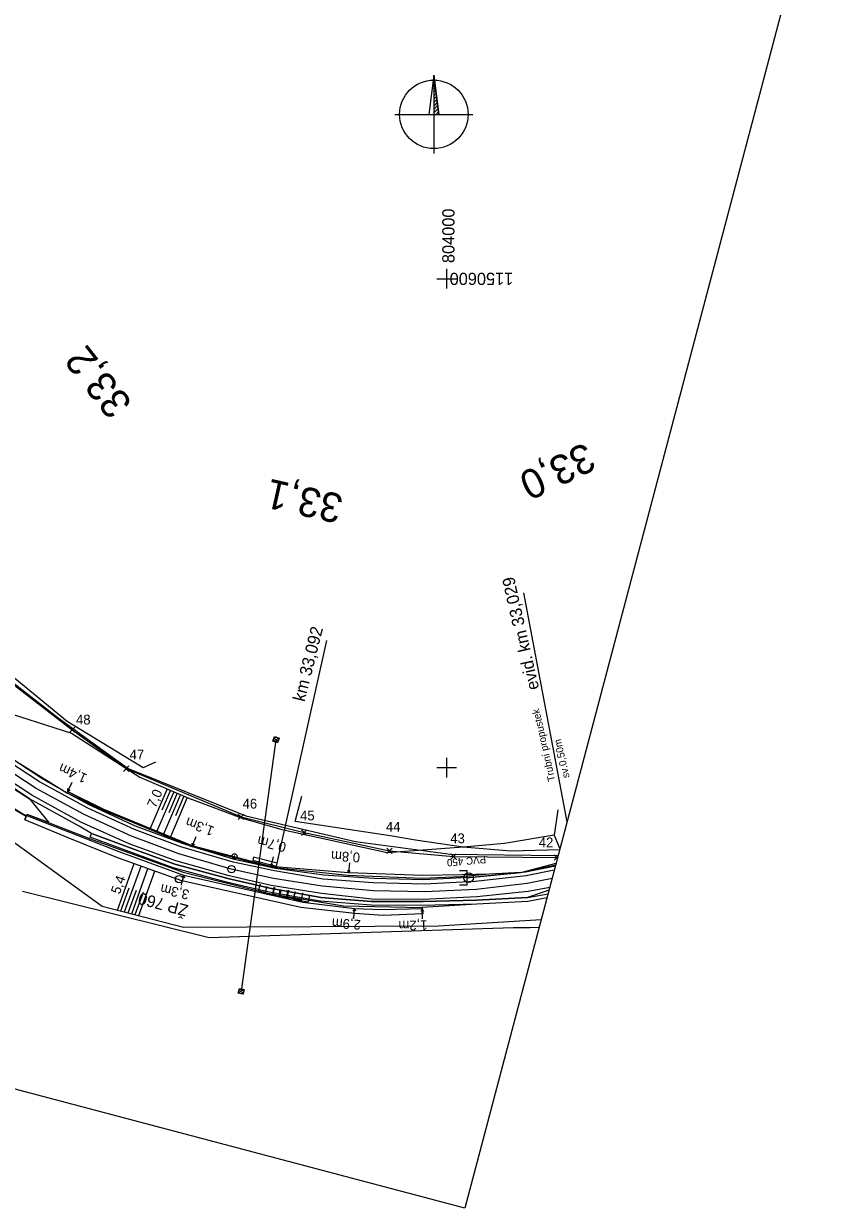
# Model space of a CAD drawing. Extents: x -805011 to -803920, y -1150790 to -1150234.
# Drawn here: x -804086.5 to -803920.3, y -1150790.1 to -1150547.8 of the extents above; entities that cross this region are included whole.
import ezdxf

# ---------------------------------------------------------------- set-up
doc = ezdxf.new("R2010")
doc.units = 0
for name, color, linetype in [('0381KM032-037P - Vrstva 1', 7, 'Continuous'), ('0381KM032-037P - Vrstva 11', 7, 'Continuous'), ('0381KM032-037P - Vrstva 13', 7, 'Continuous'), ('0381KM032-037P - Vrstva 17', 7, 'Continuous'), ('0381KM032-037P - Vrstva 19', 7, 'Continuous'), ('0381KM032-037P - Vrstva 25', 7, 'Continuous'), ('0381KM032-037P - Vrstva 4', 7, 'Continuous'), ('0381KM032-037P - Vrstva 43', 7, 'Continuous'), ('0381KM032-037P - Vrstva 44', 7, 'Continuous'), ('0381KM032-037P - Vrstva 48', 7, 'Continuous'), ('0381KM032-037P - Vrstva 49', 7, 'Continuous'), ('0381KM032-037P - Vrstva 7', 7, 'Continuous'), ('0381KM032-037P - Vrstva 9', 7, 'Continuous'), ('Default', 7, 'Continuous'), ('formát', 7, 'Continuous'), ('hran DP - hran DP', 7, 'Continuous'), ('krizky_1000 - souradnice', 7, 'Continuous'), ('krizky_1000 - Vrstva 1', 7, 'Continuous'), ('PSR_C2_2_Lomove_body_Vimperk - Vrstva 60', 7, 'Continuous'), ('PSR_C2_2_trasa_Vimperk - Kabelová trasa', 7, 'Continuous'), ('vyt_sit - stávající', 7, 'Continuous')]:
    doc.layers.add(name, color=color, linetype=linetype)

msp = doc.modelspace()

# ---------------------------------------------------------------- linework, layer by layer
at = {"layer": '0381KM032-037P - Vrstva 1'}
msp.add_lwpolyline([(-803978.41, -1150722.71), (-803983.51, -1150723.68), (-803993.92, -1150724.91), (-804004.46, -1150725.42), (-804014.95, -1150725.21), (-804025.47, -1150724.25), (-804035.41, -1150722.67), (-804044.08, -1150720.74), (-804054.77, -1150717.61), (-804064.47, -1150714.03), (-804074.16, -1150709.61), (-804083.95, -1150704.25), (-804092.73, -1150698.52), (-804098.22, -1150694.46), (-804106.33, -1150687.73), (-804113.82, -1150680.6), (-804121.06, -1150672.62)], dxfattribs=at)
at = {"layer": '0381KM032-037P - Vrstva 11'}
for p, q in [((-804034.26, -1150693.99), (-804035.54, -1150694.57)), ((-804034.75, -1150693.8), (-804035.36, -1150694.08)), ((-804034.44, -1150694.48), (-804035.04, -1150694.76)), ((-804041.41, -1150745.38), (-804042.6, -1150746.13)), ((-804041.93, -1150745.26), (-804042.49, -1150745.62)), ((-804041.53, -1150745.9), (-804042.08, -1150746.25))]:
    msp.add_line(p, q, dxfattribs=at)
for points in [[(-804034.6, -1150694.92), (-804035.54, -1150694.57), (-804035.19, -1150693.64), (-804034.25, -1150693.98)], [(-804041.63, -1150746.35), (-804042.61, -1150746.13), (-804042.39, -1150745.16), (-804041.41, -1150745.38)]]:
    msp.add_lwpolyline(points, close=True, dxfattribs=at)
at = {"layer": '0381KM032-037P - Vrstva 13'}
for p, q in [((-804076.66, -1150703.07), (-804077.51, -1150704.88)), ((-804090.39, -1150707.37), (-804086.01, -1150709.92)), ((-804086.01, -1150709.9), (-804090.31, -1150707.26)), ((-804086.01, -1150709.9), (-804085.89, -1150709.55)), ((-804086.01, -1150709.92), (-804086.01, -1150709.9)), ((-804085.98, -1150709.77), (-804085.89, -1150709.55)), ((-804051.27, -1150714.14), (-804052.03, -1150715.99)), ((-804035.82, -1150720.44), (-804051.93, -1150716.22)), ((-804035.5, -1150718.26), (-804035.97, -1150720.21)), ((-804019.87, -1150719.5), (-804020.03, -1150721.49)), ((-804054.2, -1150724.02), (-804053.75, -1150722.07)), ((-804018.95, -1150730.84), (-804018.83, -1150728.85)), ((-804004.99, -1150728.9), (-804004.87, -1150729.93)), ((-804004.95, -1150730.9), (-804004.99, -1150728.9))]:
    msp.add_line(p, q, dxfattribs=at)
for points in [[(-804052.03, -1150715.99), (-804070.24, -1150708.52), (-804077.53, -1150704.87), (-804077.68, -1150705.14), (-804070.39, -1150708.64), (-804052.3, -1150716.03), (-804051.93, -1150716.22)], [(-804077.57, -1150704.3), (-804077.51, -1150704.88), (-804077.03, -1150704.55)], [(-804085.98, -1150709.77), (-804086.01, -1150709.92), (-804086.24, -1150710.7)], [(-804004.99, -1150728.9), (-804013.04, -1150729.07), (-804018.83, -1150728.85), (-804029.4, -1150727.62), (-804053.75, -1150722.07), (-804066.98, -1150717.23), (-804077.05, -1150713.27), (-804085.98, -1150709.77)], [(-804085.89, -1150709.55), (-804073.05, -1150714.48), (-804053.9, -1150721.4), (-804036.64, -1150725.7), (-804021.1, -1150728.28), (-804004.99, -1150728.61), (-804004.87, -1150729.93)], [(-804004.87, -1150729.93), (-804012.98, -1150730.26), (-804018.76, -1150729.81), (-804029.79, -1150728.64), (-804054.15, -1150723.15), (-804067.44, -1150718.36), (-804077.42, -1150714.36), (-804086.24, -1150710.7)], [(-804072.89, -1150714.19), (-804072.63, -1150713.44), (-804065.3, -1150716.18), (-804055.61, -1150719.76), (-804044.75, -1150722.66), (-804036.16, -1150724.67), (-804025.7, -1150726.54), (-804015.38, -1150727.38), (-804004.78, -1150727.4), (-803993.85, -1150727.11), (-803983.42, -1150726.57), (-803979.23, -1150725.8)], [(-803979.45, -1150726.65), (-803983.37, -1150727.37), (-803993.84, -1150727.91), (-804005.29, -1150728.22), (-804015.43, -1150728.15), (-804025.86, -1150727.31), (-804036.32, -1150725.46), (-804045.02, -1150723.43), (-804055.91, -1150720.49), (-804065.55, -1150716.94), (-804072.89, -1150714.19)], [(-804052.11, -1150715.42), (-804052.03, -1150715.99), (-804051.56, -1150715.64)], [(-803991.2, -1150721.8), (-803996.89, -1150721.92), (-804004.84, -1150722.06), (-804020.03, -1150721.49), (-804035.97, -1150720.21), (-804052.03, -1150715.99)], [(-804036.15, -1150719.65), (-804035.97, -1150720.21), (-804035.56, -1150719.79)], [(-804053.57, -1150722.62), (-804053.75, -1150722.07), (-804054.16, -1150722.49)], [(-803991.2, -1150721.8), (-803997.06, -1150722.33), (-804004.97, -1150722.65), (-804020.12, -1150722.09), (-804035.82, -1150720.44)], [(-804020.29, -1150720.97), (-804020.03, -1150721.49), (-804019.69, -1150721.02)], [(-804018.56, -1150729.36), (-804018.83, -1150728.85), (-804019.16, -1150729.33)], [(-804004.68, -1150729.4), (-804004.99, -1150728.9), (-804005.28, -1150729.41)], [(-804004.99, -1150728.9), (-804004.99, -1150728.9), (-804004.99, -1150728.9), (-804004.99, -1150728.61)]]:
    msp.add_lwpolyline(points, dxfattribs=at)
at = {"layer": '0381KM032-037P - Vrstva 17'}
for points in [[(-804059.54, -1150698.86), (-804062.04, -1150700.07), (-804077.59, -1150690.55), (-804099.12, -1150672.95)], [(-803996.63, -1150716.3), (-804006.34, -1150714.83), (-804011.55, -1150713.97), (-804030.97, -1150711.02), (-804029.61, -1150705.83)], [(-803977.22, -1150708.65), (-803977.99, -1150713.83)], [(-803977.99, -1150713.83), (-803976.8, -1150716.64)], [(-803976.84, -1150716.79), (-803986.83, -1150717.08), (-803996.63, -1150716.3)]]:
    msp.add_lwpolyline(points, dxfattribs=at)
at = {"layer": '0381KM032-037P - Vrstva 19'}
msp.add_line((-803975.34, -1150711.1), (-803984.23, -1150664.27), dxfattribs=at)
at = {"layer": '0381KM032-037P - Vrstva 25'}
msp.add_line((-804034.9, -1150694.28), (-804042.01, -1150745.75), dxfattribs=at)
at = {"layer": '0381KM032-037P - Vrstva 4'}
for points in [[(-804075.18, -1150711.95), (-804085.34, -1150706.36), (-804094.07, -1150700.58), (-804099.68, -1150696.17), (-804107.82, -1150689.29), (-804115.4, -1150682.25), (-804122.72, -1150674.01), (-804129.15, -1150665.64), (-804135, -1150656.89)], [(-804074.79, -1150711.15), (-804084.84, -1150705.62), (-804093.69, -1150699.81), (-804099.23, -1150695.65), (-804107.33, -1150688.8), (-804114.94, -1150681.73), (-804122.23, -1150673.64), (-804128.61, -1150665.3), (-804134.56, -1150656.61)], [(-804073.38, -1150708.29), (-804083.27, -1150702.88), (-804091.89, -1150697.28), (-804097.27, -1150693.2), (-804105.34, -1150686.53), (-804112.64, -1150679.57), (-804120.03, -1150671.79), (-804126.35, -1150663.48), (-804132.06, -1150655.06)], [(-804073.1, -1150707.59), (-804077.68, -1150705.14), (-804082.78, -1150702.25), (-804091.44, -1150696.56), (-804096.83, -1150692.65), (-804104.73, -1150685.98), (-804112.1, -1150679.17), (-804119.6, -1150671.34), (-804125.86, -1150663.1), (-804131.6, -1150654.76)], [(-803977.73, -1150720.15), (-803983.88, -1150721.36), (-803994.18, -1150722.4), (-804004.64, -1150722.95), (-804014.86, -1150722.69), (-804025.14, -1150721.99), (-804034.98, -1150720.62), (-804043.41, -1150718.77), (-804051.93, -1150716.22), (-804054.24, -1150715.48), (-804063.6, -1150711.99), (-804073.1, -1150707.59)], [(-803977.96, -1150721), (-803983.73, -1150722.13), (-803994.13, -1150723.26), (-804004.52, -1150723.87), (-804015.05, -1150723.54), (-804025.27, -1150722.78), (-804035.17, -1150721.13), (-804043.67, -1150719.32), (-804054.39, -1150716.19), (-804063.83, -1150712.64), (-804073.38, -1150708.29)], [(-803979.03, -1150725.06), (-803983.42, -1150726.57), (-803993.85, -1150727.11), (-804004.78, -1150727.4), (-804015.38, -1150727.38), (-804025.7, -1150726.54), (-804036.16, -1150724.67), (-804044.75, -1150722.66), (-804055.61, -1150719.76), (-804065.3, -1150716.18), (-804072.63, -1150713.44), (-804075.18, -1150711.95)], [(-803978.88, -1150724.49), (-803983.32, -1150725.37), (-803993.82, -1150726.43), (-804004.8, -1150726.96), (-804015.29, -1150726.92), (-804025.6, -1150725.76), (-804035.88, -1150724.11), (-804044.5, -1150722.13), (-804055.4, -1150719.07), (-804064.95, -1150715.56), (-804074.79, -1150711.15)]]:
    msp.add_lwpolyline(points, dxfattribs=at)
at = {"layer": '0381KM032-037P - Vrstva 43'}
for points in [[(-803997.39, -1150721.01), (-803995.89, -1150721.01), (-803995.89, -1150724.01), (-803997.39, -1150724.01)], [(-804035.17, -1150724.55), (-804035.58, -1150726), (-804038.46, -1150725.19), (-804038.06, -1150723.74)], [(-804033.84, -1150725), (-804034.23, -1150726.45), (-804037.12, -1150725.67), (-804036.73, -1150724.22)], [(-804032.32, -1150725.04), (-804032.63, -1150726.51), (-804035.56, -1150725.9), (-804035.26, -1150724.43)], [(-804031.05, -1150725.35), (-804031.24, -1150726.84), (-804034.22, -1150726.45), (-804034.02, -1150724.96)], [(-804029.49, -1150725.62), (-804029.77, -1150727.09), (-804032.72, -1150726.52), (-804032.43, -1150725.05)], [(-804028.05, -1150726.05), (-804028.31, -1150727.53), (-804031.27, -1150727.01), (-804031.01, -1150725.53)]]:
    msp.add_lwpolyline(points, dxfattribs=at)
msp.add_circle((-803995.51, -1150722.5), 1, dxfattribs=at)
at = {"layer": '0381KM032-037P - Vrstva 44'}
msp.add_lwpolyline([(-803995.89, -1150722.51), (-803984.82, -1150721.44), (-803977.57, -1150719.55)], dxfattribs=at)
at = {"layer": '0381KM032-037P - Vrstva 48'}
for p, q in [((-804057.18, -1150704.34), (-804060.65, -1150712.45)), ((-804055.8, -1150704.93), (-804059.26, -1150713.02)), ((-804056.49, -1150704.63), (-804058.22, -1150708.69)), ((-804055.11, -1150705.22), (-804056.84, -1150709.27)), ((-804054.42, -1150705.52), (-804057.88, -1150713.59)), ((-804053.04, -1150706.11), (-804056.49, -1150714.16)), ((-804053.73, -1150705.81), (-804055.46, -1150709.84)), ((-804067.33, -1150729.13), (-804063.91, -1150719.64)), ((-804065.87, -1150729.51), (-804062.5, -1150720.14)), ((-804064.41, -1150729.89), (-804061.08, -1150720.65)), ((-804062.95, -1150730.26), (-804059.67, -1150721.16)), ((-804066.6, -1150729.32), (-804064.9, -1150724.6)), ((-804065.14, -1150729.7), (-804063.46, -1150725.05)), ((-804063.68, -1150730.07), (-804062.03, -1150725.49))]:
    msp.add_line(p, q, dxfattribs=at)
at = {"layer": '0381KM032-037P - Vrstva 49'}
msp.add_line((-804001.62, -1150732.39), (-803980.62, -1150731.04), dxfattribs=at)
for points in [[(-804216.26, -1150515.03), (-804196.49, -1150533.54), (-804188.66, -1150542.31), (-804183.72, -1150548.22), (-804177, -1150556.4), (-804165.66, -1150573.06), (-804155.49, -1150590.5), (-804146.45, -1150604.86), (-804136.37, -1150622.31), (-804131.91, -1150629.82), (-804122.71, -1150645.64), (-804115.71, -1150666.79), (-804102.89, -1150677.06), (-804092.51, -1150687.92), (-804076.71, -1150692.97), (-804062.72, -1150701.97), (-804052.08, -1150706.52)], [(-804191.88, -1150555.68), (-804187.09, -1150562.15), (-804183.47, -1150572.06), (-804177.47, -1150586.83), (-804171.32, -1150602.68), (-804162.19, -1150629.63), (-804127.41, -1150694.05), (-804117.85, -1150694.76), (-804107.49, -1150702.04), (-804103.03, -1150704.73), (-804070.42, -1150728.33), (-804053.81, -1150732.63), (-804001.62, -1150732.39)], [(-804171.89, -1150581.01), (-804161.29, -1150603.14), (-804153.71, -1150619.99), (-804149.71, -1150629.27), (-804147.81, -1150633.31), (-804145.48, -1150638.07), (-804140.73, -1150647.62), (-804139.02, -1150650.67), (-804131.55, -1150663.46), (-804125.32, -1150670.91), (-804120.07, -1150678.75), (-804110.3, -1150687.62), (-804101.36, -1150694.88), (-804099.68, -1150696.17), (-804094.07, -1150700.58), (-804090.5, -1150703.01), (-804085.34, -1150706.36), (-804081.43, -1150711.18)], [(-804087.29, -1150699.16), (-804077.68, -1150705.14), (-804077.53, -1150704.87), (-804070.24, -1150708.52), (-804052.03, -1150715.99)], [(-803977.22, -1150708.65), (-803977.99, -1150713.83), (-803988.17, -1150715.55), (-803996.63, -1150716.3), (-804012.18, -1150717.41), (-804033.61, -1150712.69), (-804041.95, -1150710.32), (-804052.08, -1150706.52)], [(-803979.45, -1150726.65), (-803983.37, -1150727.37), (-803993.84, -1150727.91), (-804004.99, -1150728.61), (-804004.87, -1150729.93), (-804012.98, -1150730.26), (-804018.76, -1150729.81), (-804029.79, -1150728.64), (-804054.15, -1150723.15), (-804067.44, -1150718.36), (-804077.42, -1150714.36), (-804086.24, -1150710.7), (-804086.01, -1150709.92)], [(-804086.01, -1150709.92), (-804086.01, -1150709.9), (-804085.89, -1150709.55), (-804081.43, -1150711.18)], [(-803984.82, -1150721.44), (-803991.2, -1150721.8), (-803996.89, -1150721.92), (-804004.84, -1150722.06), (-804020.03, -1150721.49), (-804035.97, -1150720.21), (-804052.03, -1150715.99)], [(-803984.82, -1150721.44), (-803977.66, -1150719.89)]]:
    msp.add_lwpolyline(points, dxfattribs=at)
at = {"layer": '0381KM032-037P - Vrstva 7'}
msp.add_line((-804043.32, -1150718.13), (-804043.42, -1150718.1), dxfattribs=at)
for centre, radius in [((-804043.99, -1150720.76), 0.75), ((-804043.37, -1150718.12), 0.5)]:
    msp.add_circle(centre, radius, dxfattribs=at)
at = {"layer": '0381KM032-037P - Vrstva 9'}
for p, q in [((-804034.8, -1150720.15), (-804024.5, -1150674.02)), ((-804039.51, -1150718.34), (-804039.66, -1150718.92)), ((-804039.66, -1150718.92), (-804034.81, -1150720.14)), ((-804034.66, -1150719.56), (-804039.51, -1150718.34)), ((-804034.81, -1150720.14), (-804034.66, -1150719.56)), ((-804034.66, -1150719.56), (-804034.52, -1150718.98))]:
    msp.add_line(p, q, dxfattribs=at)
at = {"layer": 'formát'}
for p, q in [((-803920.28, -1150503.02), (-803996.25, -1150790.14)), ((-804002.61, -1150558.37), (-804002.61, -1150574.37)), ((-804002.61, -1150559.01), (-804002.54, -1150558.94)), ((-804002.61, -1150559.72), (-804002.47, -1150559.57)), ((-804002.61, -1150560.42), (-804002.39, -1150560.19)), ((-804002.61, -1150561.13), (-804002.31, -1150560.82)), ((-804002.61, -1150561.84), (-804002.23, -1150561.45)), ((-804002.61, -1150562.54), (-804002.15, -1150562.08)), ((-804002.61, -1150563.25), (-804002.07, -1150562.71)), ((-804002.61, -1150563.96), (-804001.99, -1150563.34)), ((-804002.61, -1150564.67), (-804001.92, -1150563.97)), ((-804002.61, -1150565.37), (-804001.84, -1150564.59)), ((-804010.61, -1150566.37), (-803994.61, -1150566.37)), ((-804002.61, -1150566.08), (-804001.76, -1150565.22)), ((-804002.2, -1150566.37), (-804001.68, -1150565.85)), ((-803996.25, -1150790.14), (-804199.27, -1150736.42))]:
    msp.add_line(p, q, dxfattribs=at)
for points in [[(-804002.61, -1150558.37), (-804003.61, -1150566.37)], [(-804002.61, -1150558.37), (-804001.61, -1150566.37)], [(-804002.61, -1150558.37), (-804002.61, -1150566.37), (-804001.61, -1150566.37), (-804002.61, -1150558.37)]]:
    msp.add_lwpolyline(points, dxfattribs=at)
msp.add_circle((-804002.61, -1150566.37), 7, dxfattribs=at)
at = {"layer": 'hran DP - hran DP'}
for p, q in [((-804092.1, -1150680), (-804079.43, -1150689.81)), ((-804079.43, -1150689.81), (-804065.16, -1150700.21)), ((-804065.16, -1150700.21), (-804041.05, -1150709.83)), ((-804041.05, -1150709.83), (-804018.63, -1150715.09)), ((-804018.63, -1150715.09), (-803999.22, -1150717.72)), ((-803999.22, -1150717.72), (-803977.16, -1150717.98)), ((-804048.58, -1150734.81), (-804086.77, -1150725.31)), ((-803986.36, -1150732.8), (-804048.58, -1150734.81)), ((-803982.91, -1150732.74), (-803986.36, -1150732.8)), ((-803981.05, -1150732.7), (-803982.91, -1150732.74))]:
    msp.add_line(p, q, dxfattribs=at)
at = {"layer": 'krizky_1000 - Vrstva 1'}
for points in [[(-804000, -1150598), (-804000, -1150602)], [(-804002, -1150600), (-803998, -1150600)], [(-804000, -1150698), (-804000, -1150702)], [(-804002, -1150700), (-803998, -1150700)]]:
    msp.add_lwpolyline(points, dxfattribs=at)
at = {"layer": 'PSR_C2_2_Lomove_body_Vimperk - Vrstva 60'}
for p, q in [((-804077.16, -1150692.84), (-804076.06, -1150691.74)), ((-804076.06, -1150692.84), (-804077.16, -1150691.74)), ((-804066.07, -1150700.76), (-804064.97, -1150699.66)), ((-804064.97, -1150700.76), (-804066.07, -1150699.66)), ((-804042.6, -1150710.62), (-804041.5, -1150709.52)), ((-804041.5, -1150710.62), (-804042.6, -1150709.52)), ((-804029.69, -1150713.85), (-804028.59, -1150712.75)), ((-804028.59, -1150713.85), (-804029.69, -1150712.75)), ((-804012.21, -1150717.54), (-804011.11, -1150716.44)), ((-804011.11, -1150717.54), (-804012.21, -1150716.44)), ((-803999.15, -1150718.71), (-803998.05, -1150717.61)), ((-803998.05, -1150718.71), (-803999.15, -1150717.61)), ((-803977.3, -1150718.53), (-803977.97, -1150717.86)), ((-803977.97, -1150718.96), (-803977.22, -1150718.21))]:
    msp.add_line(p, q, dxfattribs=at)
at = {"layer": 'PSR_C2_2_trasa_Vimperk - Kabelová trasa'}
msp.add_lwpolyline([(-804099.51, -1150673.08), (-804092.3, -1150680.21), (-804076.61, -1150692.29), (-804065.52, -1150700.21), (-804042.05, -1150710.07), (-804029.14, -1150713.3), (-804011.66, -1150716.99), (-803998.6, -1150718.16), (-803977.42, -1150718.41), (-803977.26, -1150718.37)], dxfattribs=at)
at = {"layer": 'vyt_sit - stávající'}
msp.add_line((-804054.77, -1150722.82), (-804054.67, -1150722.82), dxfattribs=at)
msp.add_circle((-804054.72, -1150722.82), 0.756, dxfattribs=at)

# ---------------------------------------------------------------- texts
at = {"layer": '0381KM032-037P - Vrstva 13'}
for s, rotation, p in [('1,4m', 156.1294, (-804073.33, -1150701.45)), ('1,3m', 159.4135, (-804047.36, -1150712.19)), ('0,7m', 165.6438, (-804032.66, -1150715.41)), ('0,8m', 176.7126, (-804017.65, -1150717.4)), ('3,3m', 167.1636, (-804052.49, -1150725.09)), ('2,9m', 176.4791, (-804017.48, -1150731.17)), ('1,2m', 181.2027, (-804003.91, -1150731.23))]:
    msp.add_text(s, height=2, rotation=rotation, dxfattribs=at).set_placement(p)
at = {"layer": '0381KM032-037P - Vrstva 19'}
for s, height, p in [('evid. km 33,029', 2.5, (-803981.04, -1150683.82)), ('Trubní propustek', 1.5, (-803977.75, -1150702.64)), ('sv.0,50m', 1.5, (-803974.83, -1150701.98))]:
    msp.add_text(s, height=height, rotation=102.69, dxfattribs=at).set_placement(p)
at = {"layer": '0381KM032-037P - Vrstva 43'}
msp.add_text('PVC 450', height=1.5, rotation=185, dxfattribs=at).set_placement((-803991.99, -1150718.03))
at = {"layer": '0381KM032-037P - Vrstva 48'}
for s, rotation, p in [('7,0', 66.8248, (-804059.51, -1150708.39)), ('5,4', 70.2002, (-804066.86, -1150726.04))]:
    msp.add_text(s, height=2, rotation=rotation, dxfattribs=at).set_placement(p)
at = {"layer": '0381KM032-037P - Vrstva 7'}
for s, rotation, p in [('33,2', 128.139, (-804064.09, -1150625.46)), ('33,0', 205.6225, (-803971.56, -1150633.32)), ('33,1', 167.4012, (-804020.85, -1150644.28))]:
    msp.add_text(s, height=6, rotation=rotation, dxfattribs=at).set_placement(p)
at = {"layer": '0381KM032-037P - Vrstva 9'}
msp.add_text('km 33,092', height=2.5, rotation=75.8763, dxfattribs=at).set_placement((-804029.06, -1150686.64))
at = {"layer": 'Default'}
for s, p in [('48', (-804075.8, -1150691.17)), ('47', (-804064.84, -1150698.32)), ('46', (-804041.73, -1150708.37)), ('45', (-804029.96, -1150710.79)), ('44', (-804012.4, -1150713.09)), ('43', (-803999.24, -1150715.47)), ('42', (-803981.13, -1150716.29))]:
    msp.add_text(s, height=2, dxfattribs=at).set_placement(p)
at = {"layer": 'krizky_1000 - souradnice'}
for s, rotation, p in [('804000', 90, (-803998.38, -1150596.79)), ('1150600', 180, (-803986.36, -1150598.77))]:
    msp.add_text(s, height=2.5, rotation=rotation, dxfattribs=at).set_placement(p)
at = {"layer": 'vyt_sit - stávající'}
msp.add_text('ŽP 760', height=2.4, rotation=165, dxfattribs=at).set_placement((-804052.69, -1150728.18))

doc.saveas('drawing.dxf')
